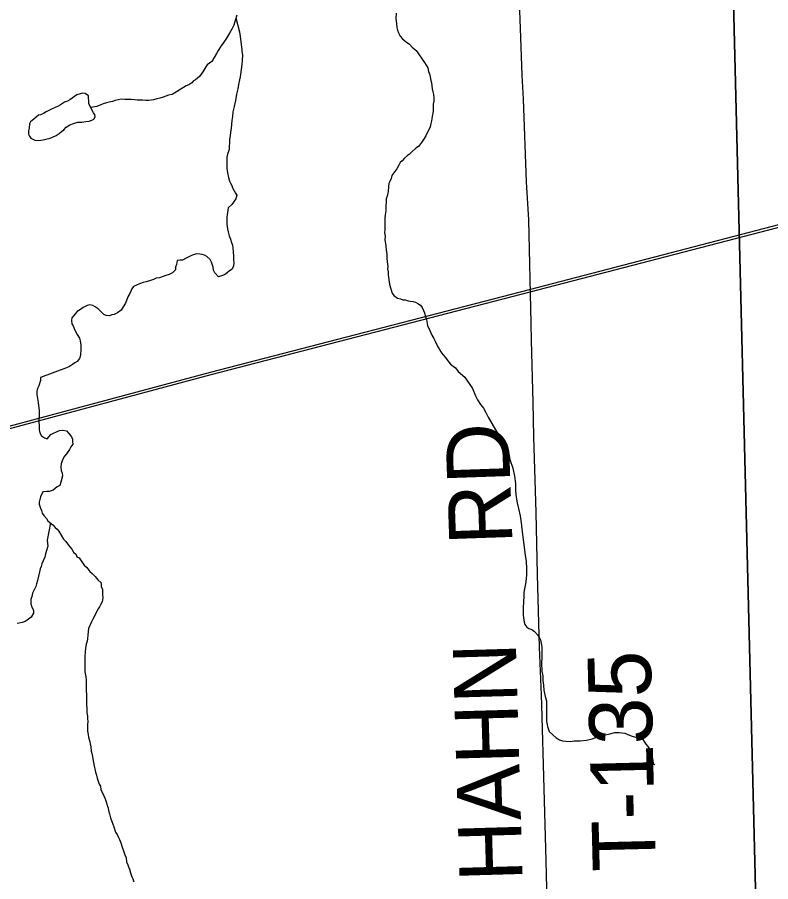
# Model space of a CAD drawing. Extents: x 0 to 34, y 0 to 22.
# Drawn here: x 7.68 to 8.358, y 17.589 to 18.367 of the extents above; entities that cross this region are included whole.
import ezdxf

# ---------------------------------------------------------------- set-up
doc = ezdxf.new("R2010")
doc.units = 0
for name, color, linetype in [('GM_X_Corporation', 7, 'Continuous'), ('GM_X_Minor_Lake', 7, 'Continuous'), ('GM_X_Minor_River', 7, 'Continuous'), ('GM_X_Rail_Line', 7, 'Continuous'), ('GM_X_Township_Road', 7, 'Continuous'), ('GM_X_Township_Road_Text', 7, 'Continuous')]:
    doc.layers.add(name, color=color, linetype=linetype)

msp = doc.modelspace()

# ---------------------------------------------------------------- linework, layer by layer
at = {"layer": 'GM_X_Corporation'}
for points in [[(8.34448, 17.55856), (8.31964, 18.56207)], [(8.31964, 18.56207), (8.34448, 17.55856)]]:
    msp.add_lwpolyline(points, dxfattribs=at)
at = {"layer": 'GM_X_Minor_Lake'}
for points in [[(7.74417, 18.28913), (7.74419, 18.2918), (7.74384, 18.29408), (7.74386, 18.29636), (7.74084, 18.29829), (7.73856, 18.29869), (7.73627, 18.29795), (7.73322, 18.29722), (7.73131, 18.29572), (7.72709, 18.29272), (7.7248, 18.2916), (7.72213, 18.29048), (7.71868, 18.28823), (7.71639, 18.28711)], [(7.71639, 18.28711), (7.71104, 18.2845), (7.70875, 18.28338), (7.70569, 18.28189), (7.7034, 18.28039), (7.70072, 18.27927), (7.69882, 18.27891), (7.6946, 18.27515), (7.69153, 18.27289), (7.69076, 18.271), (7.69034, 18.2672), (7.68994, 18.26492), (7.6899, 18.26188), (7.69065, 18.25997), (7.69177, 18.25806), (7.69366, 18.25728), (7.69555, 18.2565), (7.69897, 18.25609), (7.70088, 18.25645), (7.70316, 18.25681), (7.70544, 18.25717), (7.70926, 18.25827), (7.71155, 18.25901), (7.7146, 18.26051), (7.71728, 18.26238), (7.71958, 18.26426), (7.7215, 18.26577), (7.7238, 18.26803), (7.72687, 18.27028), (7.7303, 18.27139), (7.73411, 18.27249), (7.73602, 18.27248), (7.73792, 18.27246), (7.74135, 18.27319), (7.74439, 18.27354), (7.74668, 18.27428), (7.74859, 18.2754), (7.74975, 18.27729), (7.74939, 18.27958), (7.74827, 18.28111), (7.74417, 18.28913)]]:
    msp.add_lwpolyline(points, dxfattribs=at)
at = {"layer": 'GM_X_Minor_River'}
for points in [[(7.87728, 18.36889), (7.87571, 18.36396), (7.87453, 18.35979), (7.87298, 18.35676), (7.87065, 18.3526), (7.86795, 18.34806), (7.86563, 18.34466), (7.86331, 18.34126), (7.86061, 18.3371), (7.85906, 18.33445), (7.85481, 18.32727), (7.8506, 18.32426), (7.84944, 18.32237), (7.84673, 18.31783), (7.84365, 18.31368), (7.84019, 18.31067), (7.83829, 18.30993), (7.83675, 18.30804), (7.83406, 18.30616), (7.83178, 18.30542), (7.81915, 18.29756), (7.81572, 18.29683), (7.81114, 18.29497), (7.80809, 18.29424), (7.80542, 18.2935), (7.80238, 18.29277), (7.80009, 18.29241), (7.79819, 18.29205), (7.79553, 18.29207), (7.79249, 18.29248), (7.79059, 18.2925), (7.78754, 18.29253), (7.78526, 18.29255), (7.78223, 18.29296), (7.77881, 18.29299), (7.77652, 18.29301), (7.77311, 18.29343), (7.77044, 18.29269), (7.76777, 18.29195), (7.76548, 18.29121), (7.76243, 18.29048), (7.76015, 18.29013), (7.75709, 18.28901), (7.7548, 18.28827), (7.75137, 18.28678), (7.74592, 18.2857)], [(8.02063, 18.37058), (8.02021, 18.36602), (8.02056, 18.36374), (8.02092, 18.36107), (8.02126, 18.35765), (8.022, 18.35536), (8.02274, 18.35307), (8.02423, 18.35001), (8.02649, 18.34771), (8.02874, 18.3454), (8.03252, 18.34271), (8.03515, 18.34002), (8.03854, 18.33694), (8.04005, 18.33503), (8.04454, 18.32852), (8.04604, 18.32622), (8.04754, 18.32393), (8.04904, 18.32163), (8.04976, 18.3182), (8.05087, 18.31515), (8.05123, 18.31324), (8.05196, 18.3102), (8.05232, 18.30791), (8.05267, 18.30524), (8.05303, 18.30258), (8.05376, 18.29991), (8.05412, 18.29762), (8.05446, 18.29458), (8.05443, 18.29153), (8.05403, 18.28888), (8.05401, 18.28698), (8.05399, 18.28507), (8.05397, 18.28317), (8.05356, 18.28051), (8.05316, 18.27785), (8.05275, 18.27558), (8.05235, 18.27368), (8.05195, 18.2714), (8.05116, 18.26837), (8.04728, 18.26041), (8.04534, 18.25701), (8.04341, 18.25437), (8.04072, 18.25059), (8.03842, 18.24909), (8.03458, 18.2457), (8.03266, 18.24382), (8.03075, 18.24269), (8.02806, 18.24006), (8.02614, 18.23779), (8.02422, 18.23629), (8.02306, 18.23402), (8.02112, 18.23061), (8.01842, 18.22684), (8.01688, 18.22457), (8.01609, 18.22191), (8.01493, 18.21926), (8.01415, 18.21737), (8.01374, 18.21471), (8.01331, 18.21015), (8.01251, 18.20597), (8.01173, 18.2037), (8.0117, 18.20066), (8.01128, 18.19724), (8.01124, 18.19267), (8.01082, 18.18926), (8.01041, 18.18583), (8.01038, 18.18279), (8.01035, 18.17975), (8.01031, 18.17595), (8.01028, 18.1729), (8.01063, 18.16986), (8.0106, 18.16682), (8.01094, 18.16339), (8.01129, 18.16072), (8.01164, 18.15768), (8.01236, 18.15349), (8.01233, 18.15006), (8.01268, 18.14702), (8.01302, 18.14283), (8.01299, 18.14055), (8.01335, 18.13788)], [(7.87653, 18.36652), (7.87979, 18.35403), (7.88049, 18.34756), (7.8812, 18.34261), (7.88155, 18.33995), (7.88191, 18.33804), (7.88189, 18.33614), (7.88224, 18.33309), (7.88219, 18.32815), (7.88178, 18.32435), (7.88055, 18.31561), (7.88014, 18.31334), (7.87974, 18.31068), (7.87893, 18.3065), (7.87814, 18.3027), (7.87694, 18.29777), (7.87613, 18.29207), (7.87493, 18.28676), (7.87374, 18.28183), (7.87332, 18.27765), (7.8729, 18.27423), (7.87249, 18.27081), (7.87207, 18.26701), (7.87166, 18.26359), (7.87124, 18.26017), (7.87083, 18.25713), (7.87036, 18.24801), (7.8688, 18.24384), (7.86839, 18.24118), (7.86832, 18.23472), (7.86829, 18.23129), (7.86865, 18.22901), (7.86901, 18.2271), (7.86973, 18.22291), (7.87083, 18.21948), (7.87157, 18.21757), (7.8727, 18.21566), (7.87343, 18.21337), (7.87492, 18.21069), (7.87605, 18.20878), (7.87717, 18.20687), (7.87637, 18.20345), (7.8729, 18.19854), (7.86945, 18.19553), (7.86823, 18.18717), (7.86818, 18.18261), (7.86816, 18.18071), (7.86888, 18.17652), (7.86961, 18.17385), (7.87034, 18.17042), (7.87145, 18.16737), (7.87256, 18.16431), (7.8733, 18.16202), (7.87365, 18.15936), (7.87399, 18.15593), (7.87434, 18.15213), (7.87431, 18.14908), (7.87465, 18.14604), (7.87425, 18.14338), (7.87308, 18.14035), (7.87078, 18.13885), (7.86848, 18.13697), (7.86618, 18.13509), (7.86084, 18.13324), (7.85746, 18.13707), (7.85634, 18.13936), (7.85598, 18.14203), (7.85451, 18.14661), (7.85339, 18.1489), (7.85038, 18.15159), (7.84811, 18.15275), (7.84621, 18.15353), (7.84394, 18.15393), (7.84128, 18.15396), (7.83785, 18.15323), (7.83517, 18.15211), (7.83097, 18.14987), (7.82829, 18.14838), (7.82639, 18.14839), (7.82373, 18.14804), (7.82293, 18.14462), (7.82215, 18.14197), (7.82212, 18.13969), (7.81943, 18.13705), (7.81638, 18.13556), (7.81332, 18.13445), (7.81104, 18.13371), (7.8076, 18.1326), (7.80456, 18.13224), (7.80227, 18.13113), (7.79883, 18.12964), (7.79578, 18.12891), (7.79311, 18.12817), (7.78968, 18.12706), (7.78433, 18.12483), (7.78279, 18.12256), (7.78085, 18.1184)], [(8.01335, 18.13788), (8.01332, 18.13522), (8.01368, 18.13332), (8.01403, 18.13065), (8.01475, 18.12684), (8.01548, 18.12341), (8.01696, 18.11883), (8.01845, 18.11654), (8.02185, 18.11423), (8.0245, 18.11344), (8.02678, 18.11266), (8.02868, 18.11264), (8.03133, 18.11185), (8.03323, 18.11145), (8.03589, 18.11105), (8.03816, 18.11065), (8.04005, 18.10949), (8.0427, 18.10794), (8.0442, 18.10565), (8.04531, 18.10297), (8.04605, 18.10106), (8.04679, 18.09839), (8.04789, 18.09496), (8.04898, 18.08963), (8.05083, 18.08505), (8.05269, 18.08084), (8.05456, 18.07778), (8.05568, 18.07549), (8.05829, 18.07052), (8.05941, 18.06861), (8.06091, 18.06593), (8.06278, 18.06363), (8.06466, 18.06095), (8.06729, 18.05788), (8.06954, 18.05482), (8.0718, 18.0529), (8.07407, 18.05136), (8.07631, 18.04829), (8.08233, 18.04295)], [(7.78085, 18.1184), (7.7793, 18.11537), (7.77696, 18.10969), (7.77502, 18.10628), (7.77309, 18.10326), (7.77003, 18.101), (7.76697, 18.09951), (7.76468, 18.09915), (7.76278, 18.09841), (7.75974, 18.09844), (7.75746, 18.0996), (7.75521, 18.1019), (7.75257, 18.10459), (7.74993, 18.10652), (7.74766, 18.10768), (7.745, 18.10809), (7.74272, 18.10773), (7.7389, 18.10586), (7.7366, 18.10398), (7.73354, 18.10211), (7.72892, 18.09645), (7.72852, 18.09417), (7.72887, 18.09112), (7.72999, 18.08921), (7.73147, 18.08539), (7.73371, 18.08157), (7.73558, 18.07813), (7.73631, 18.07584), (7.73704, 18.07203), (7.737, 18.06823), (7.73656, 18.0629), (7.73578, 18.05987), (7.73347, 18.05723), (7.73155, 18.0561), (7.72926, 18.05461), (7.72658, 18.05273), (7.7239, 18.05161), (7.70064, 18.04268)], [(7.70064, 18.04268), (7.70064, 18.04019), (7.69917, 18.03523), (7.69805, 18.03293), (7.69731, 18.03064), (7.69735, 18.0276), (7.69774, 18.0257), (7.69856, 18.02038), (7.69896, 18.01772), (7.69939, 18.01354), (7.69941, 18.01088), (7.69944, 18.00821), (7.69909, 18.00554), (7.69911, 18.00288), (7.69953, 17.99946), (7.69956, 17.99566), (7.69997, 17.993), (7.70152, 17.99035), (7.7042, 17.98848), (7.70649, 17.98774), (7.70987, 17.99158), (7.71176, 17.99236), (7.71554, 17.9943), (7.71782, 17.99509), (7.72085, 17.9955), (7.7239, 17.99477), (7.72621, 17.99251), (7.72852, 17.98949), (7.7293, 17.98721), (7.72932, 17.98531), (7.72973, 17.98265), (7.72785, 17.98035), (7.72673, 17.97806), (7.72411, 17.97422), (7.72223, 17.97192), (7.72111, 17.97001), (7.71999, 17.96771), (7.71926, 17.96504), (7.71891, 17.96199), (7.71932, 17.95895), (7.7201, 17.95667), (7.72051, 17.9544), (7.71904, 17.94867), (7.71793, 17.94562), (7.71566, 17.94445), (7.71189, 17.94137), (7.70849, 17.94019), (7.7062, 17.94017), (7.70279, 17.93975), (7.70055, 17.93554), (7.69946, 17.93058), (7.69948, 17.92868), (7.70065, 17.92527), (7.70143, 17.92299), (7.70222, 17.92072), (7.70376, 17.91845), (7.70607, 17.91581), (7.70723, 17.91392), (7.70914, 17.91242), (7.71183, 17.91016), (7.71375, 17.9079), (7.71567, 17.9064), (7.71721, 17.90451), (7.72146, 17.89733), (7.72338, 17.89506), (7.72569, 17.89204), (7.72723, 17.89016), (7.72877, 17.88827), (7.73032, 17.88562), (7.73262, 17.88336), (7.7334, 17.88147), (7.73531, 17.88035), (7.73724, 17.8777), (7.73994, 17.87393), (7.74224, 17.87167), (7.74494, 17.86827), (7.74724, 17.86639), (7.74992, 17.86376), (7.75224, 17.86074), (7.75531, 17.8581), (7.75534, 17.85468), (7.75651, 17.85203), (7.75653, 17.85013), (7.75655, 17.84746), (7.75658, 17.84442), (7.75624, 17.84099), (7.75474, 17.83831), (7.75362, 17.8364), (7.7525, 17.83448), (7.75101, 17.8318), (7.74914, 17.82798), (7.74765, 17.8253), (7.74653, 17.823), (7.74393, 17.81689), (7.74323, 17.81117), (7.74289, 17.80774), (7.74253, 17.80546), (7.74179, 17.80278), (7.74107, 17.79897), (7.74072, 17.79592), (7.74038, 17.79173)], [(8.08233, 18.04295), (8.08922, 18.03284), (8.09194, 18.0264), (8.09388, 18.02262), (8.09658, 18.01846), (8.09928, 18.01506), (8.10122, 18.01128), (8.10354, 18.00712), (8.10664, 18.00144), (8.11012, 17.99577), (8.11398, 17.98934), (8.11823, 17.98291), (8.12132, 17.97762), (8.12293, 17.96888), (8.12567, 17.9613), (8.12726, 17.95409), (8.12809, 17.94725), (8.12815, 17.94078), (8.12859, 17.93508), (8.1294, 17.93014), (8.1306, 17.92482), (8.13218, 17.91837), (8.133, 17.91191), (8.13382, 17.90621), (8.13671, 17.88303), (8.13753, 17.87733), (8.13798, 17.87087), (8.13803, 17.86554), (8.13769, 17.86173), (8.13697, 17.85715), (8.13626, 17.85258), (8.13553, 17.84915), (8.13556, 17.8461), (8.13524, 17.84077), (8.13491, 17.83544), (8.13494, 17.8324), (8.13498, 17.82897), (8.1354, 17.82479), (8.1358, 17.82251), (8.13658, 17.82062), (8.13813, 17.81797), (8.14004, 17.81685), (8.14271, 17.81612), (8.14501, 17.81424), (8.1477, 17.81122), (8.14924, 17.80895), (8.15041, 17.80668), (8.1512, 17.80365), (8.15161, 17.79985), (8.15166, 17.79528), (8.15171, 17.79072), (8.15138, 17.78577), (8.15183, 17.77854), (8.15264, 17.77398), (8.15267, 17.77018), (8.1531, 17.76599), (8.15352, 17.76143), (8.15472, 17.75574), (8.15589, 17.75195), (8.15594, 17.74776), (8.15598, 17.74319), (8.15603, 17.73863), (8.15606, 17.73596), (8.15608, 17.7333), (8.15649, 17.73064), (8.15689, 17.72874), (8.15768, 17.72609), (8.15846, 17.72419), (8.16459, 17.71855), (8.16765, 17.71668), (8.17032, 17.71595), (8.17337, 17.7156), (8.17717, 17.71526), (8.18097, 17.71568), (8.18629, 17.71573), (8.19198, 17.71655), (8.19691, 17.71775), (8.20184, 17.71932), (8.20563, 17.7205), (8.20904, 17.7213), (8.21284, 17.7221), (8.21739, 17.72329), (8.22119, 17.72333), (8.22385, 17.72297), (8.22651, 17.72262), (8.22842, 17.72188), (8.23224, 17.7204), (8.23681, 17.71892), (8.24025, 17.71744), (8.24254, 17.71708), (8.24524, 17.71292), (8.24716, 17.71066), (8.24832, 17.70877), (8.24948, 17.70688), (8.25028, 17.70308), (8.25106, 17.70081), (8.25147, 17.69853), (8.25188, 17.69549)], [(7.70974, 17.91192), (7.70664, 17.89641), (7.70707, 17.89109), (7.70635, 17.88804), (7.70524, 17.88422), (7.70451, 17.88116), (7.70303, 17.87773), (7.70192, 17.87505), (7.70118, 17.87276), (7.70044, 17.87047), (7.69971, 17.8678), (7.69788, 17.86017), (7.69715, 17.85712), (7.69642, 17.85482), (7.6953, 17.85215), (7.69344, 17.8487), (7.69271, 17.84565), (7.69197, 17.84298), (7.69199, 17.84108), (7.69201, 17.83918), (7.6928, 17.83614), (7.69435, 17.83349), (7.69437, 17.83083), (7.69213, 17.827), (7.68874, 17.8243), (7.68685, 17.82314), (7.6842, 17.82235), (7.68154, 17.82156), (7.67964, 17.82154)], [(7.74038, 17.79173), (7.74042, 17.78755), (7.74047, 17.78298), (7.74052, 17.77804), (7.74133, 17.77348), (7.74174, 17.77044), (7.74178, 17.76663), (7.74182, 17.76169), (7.74187, 17.75674), (7.74192, 17.7518), (7.74196, 17.74799), (7.74237, 17.74533), (7.74241, 17.74115), (7.74282, 17.73811), (7.74285, 17.73544), (7.74325, 17.73354), (7.7429, 17.73011), (7.74293, 17.72745), (7.74296, 17.72441), (7.74337, 17.72137), (7.74377, 17.71909), (7.74496, 17.71491), (7.74535, 17.71302), (7.74576, 17.71036), (7.74618, 17.70656), (7.74697, 17.70352), (7.74777, 17.69972), (7.74818, 17.6963), (7.74898, 17.69288), (7.74938, 17.69061), (7.75017, 17.68757), (7.75096, 17.68492), (7.75174, 17.68226), (7.75253, 17.6796), (7.75332, 17.67695), (7.75448, 17.67506), (7.75489, 17.67202), (7.7576, 17.66634), (7.75877, 17.66369), (7.75956, 17.66103), (7.76073, 17.658), (7.76152, 17.65534), (7.76192, 17.65307), (7.76271, 17.65003), (7.7635, 17.64661), (7.76468, 17.6432), (7.76663, 17.63827), (7.7682, 17.63373), (7.76974, 17.63146), (7.77091, 17.62881), (7.77168, 17.62691), (7.77286, 17.62388), (7.77403, 17.62009), (7.77521, 17.61667), (7.77639, 17.61326), (7.77755, 17.61061), (7.77797, 17.60681), (7.77914, 17.60416), (7.77992, 17.60226), (7.7807, 17.60037), (7.78149, 17.59695), (7.78267, 17.59354), (7.78382, 17.59165), (7.78461, 17.58899)], [(8.25188, 17.69549), (8.25303, 17.69436), (8.2534, 17.69474)]]:
    msp.add_lwpolyline(points, dxfattribs=at)
at = {"layer": 'GM_X_Rail_Line'}
for points in [[(5.51437, 18.17455), (5.85501, 17.96843), (6.05208, 17.85288), (6.1085, 17.82127), (6.15252, 17.80321), (6.19201, 17.7874), (6.23151, 17.77498), (6.27327, 17.76144), (6.33759, 17.7445), (6.39966, 17.73208), (6.45157, 17.7287), (6.51477, 17.72757), (6.58618, 17.72955), (6.62557, 17.73318), (6.68622, 17.74458), (6.78367, 17.76688), (6.92552, 17.80358), (7.18275, 17.87014), (7.53636, 17.96017), (7.85414, 18.04538), (8.14127, 18.11988), (8.4864, 18.20971), (8.85351, 18.30531), (8.9, 18.3175)], [(5.51559, 18.17654), (5.85621, 17.97043), (6.05324, 17.8549), (6.10952, 17.82337), (6.1534, 17.80536), (6.1928, 17.7896), (6.23222, 17.7772), (6.27393, 17.76367), (6.33812, 17.74677), (6.39997, 17.7344), (6.45167, 17.73102), (6.51476, 17.7299), (6.58604, 17.73187), (6.62525, 17.73548), (6.68574, 17.74686), (6.78312, 17.76914), (6.92494, 17.80584), (7.18217, 17.87239), (7.53576, 17.96242), (7.85354, 18.04763), (8.14068, 18.12213), (8.48581, 18.21196), (8.85292, 18.30756), (8.9, 18.3199)]]:
    msp.add_lwpolyline(points, dxfattribs=at)
at = {"layer": 'GM_X_Township_Road'}
for points in [[(8.15168, 17.74779), (8.15142, 17.75677), (8.14975, 17.80021), (8.14798, 17.86541), (8.14653, 17.92128), (8.14453, 17.9894), (8.14401, 18.02038), (8.14249, 18.07619), (8.14222, 18.09163), (8.13989, 18.18468), (8.13806, 18.21881), (8.1352, 18.29323), (8.13418, 18.31491), (8.13293, 18.34888), (8.13133, 18.38922), (8.13139, 18.41084), (8.12992, 18.44609), (8.1294, 18.45498), (8.1291, 18.47351), (8.12958, 18.4983), (8.12914, 18.51904)], [(8.15749, 17.5397), (8.15738, 17.54366), (8.15694, 17.55903), (8.15556, 17.60786), (8.15384, 17.67299), (8.15168, 17.74779)]]:
    msp.add_lwpolyline(points, dxfattribs=at)

# ---------------------------------------------------------------- texts
at = {"layer": 'GM_X_Township_Road_Text'}
for s, rotation, p in [('RD', 91.99104, (8.12537, 17.89309)), ('HAHN', 91.65653, (8.13453, 17.58978)), ('T-135', 91.41267, (8.25441, 17.59903))]:
    msp.add_text(s, height=0.056818, rotation=rotation, dxfattribs=at).set_placement(p)

doc.saveas('drawing.dxf')
